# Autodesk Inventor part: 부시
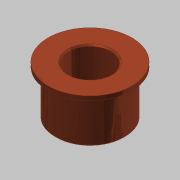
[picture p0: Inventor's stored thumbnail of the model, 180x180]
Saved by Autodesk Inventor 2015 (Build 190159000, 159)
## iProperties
Created: 2015-10
Part Number: 부시
Document SubType Name: Modeling
Designer: mdu
Density: 7.86 g/cm^3
Material: 강철, 연강
Mass: 364.706 g
Surface Area: 129.307 cm^2
Volume: 46.4003 cm^3
Appearance: 구리 - 새틴
Author: mdu
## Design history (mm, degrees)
sketch "스케치1"
  geometry: C1 r 31 at (0, 0) reference; C2 r 25 at (0, 0) reference; C3 r 30 at (0, 0) reference; 1 further point
  node "참조1"
  node "참조2"
  node "참조4"
extrude "돌출1" new body sketch "스케치1" distance "d0" = 3; taper "d1" = 0 deg
extrude "돌출2" join sketch "스케치1" distance "d2" = 35; taper "d3" = 0 deg
chamfer "모따기1" distance "d6" = 1; stored, may be unused: second distance "d7" = 2, angle "d8" = 45 deg
sketch "스케치3"
  geometry: C1 r 15 at (0, 0); 1 further point
  constraints: 1 centre point, 1 coincident
  dimensions: "d13" = 30 diameter of C1
extrude "돌출4" cut sketch "스케치3" stored distance "d14" = 10; taper "d15" = 0 deg
chamfer "모따기3" distance "d16" = 1; stored, may be unused: second distance "d17" = 2, angle "d18" = 45 deg
node "솔리드1"
